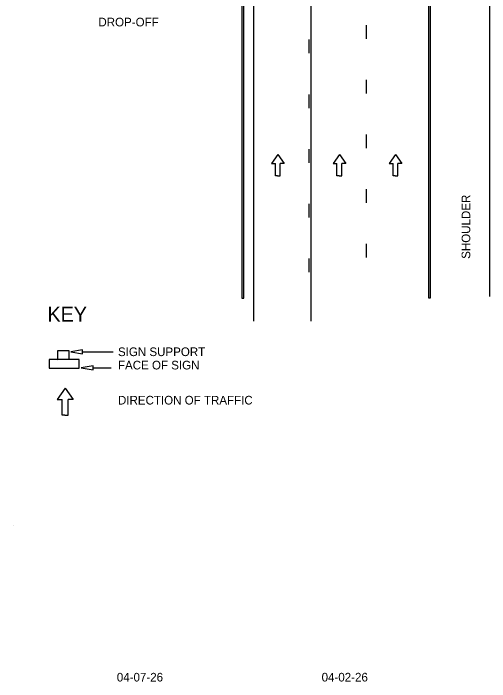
# Model space of a CAD drawing. Extents: x 1531.2 to 1543.2, y 1529.6 to 1539.7.
# Drawn here: x 1531.208 to 1534.518, y 1529.661 to 1534.302 of the extents above; entities that cross this region are included whole.
import ezdxf

# ---------------------------------------------------------------- set-up
doc = ezdxf.new("R2010")
doc.units = 0
for name, color, linetype in [('DETL-DIMS', 7, 'Continuous'), ('DETL-LINE', 7, 'Continuous'), ('DETL-NOTE', 7, 'Continuous'), ('DETL-TITL', 7, 'Continuous'), ('TTLB-TEXT', 7, 'Continuous'), ('USER-BORD', 7, 'Continuous')]:
    doc.layers.add(name, color=color, linetype=linetype)

# ---------------------------------------------------------------- blocks, each defined once
blk = doc.blocks.new('SIGN13')
at = {"layer": 'USER-BORD'}
for points in [[(-0.0134, 0.0182), (0.011, 0.0189), (0.011, 0.0371), (-0.0134, 0.0371)], [(-0.0314, 0.0182), (-0.0314, 0), (0.032, 0), (0.032, 0.0182)]]:
    blk.add_lwpolyline(points, close=True, dxfattribs=at)
blk = doc.blocks.new('DIR2')
at = {"layer": 'USER-BORD'}
for p, q in [((0, 0.0012), (-0.0342, -0.0477)), ((0, 0.0012), (0.0342, -0.0477)), ((-0.0342, -0.0477), (-0.0132, -0.0477)), ((-0.0132, -0.1133), (-0.0132, -0.0477)), ((0.0342, -0.0477), (0.0132, -0.0477)), ((0.0132, -0.1133), (0.0132, -0.0477)), ((-0.0011, -0.1133), (-0.0132, -0.1133)), ((-0.0011, -0.1133), (0.0011, -0.1133)), ((0.0011, -0.1133), (0.0132, -0.1133))]:
    blk.add_line(p, q, dxfattribs=at)
blk = doc.blocks.new('TD')
at = {"layer": 'USER-BORD'}
for p, q in [((0, 0), (-0.0539, -0.077)), ((0, 0), (0.0539, -0.077)), ((-0.0539, -0.077), (-0.0208, -0.077)), ((-0.0208, -0.1803), (-0.0208, -0.077)), ((0.0208, -0.1803), (0.0208, -0.077)), ((0.0539, -0.077), (0.0208, -0.077)), ((-0.0017, -0.1803), (-0.0208, -0.1803)), ((-0.0017, -0.1803), (0.0017, -0.1803)), ((0.0017, -0.1803), (0.0208, -0.1803))]:
    blk.add_line(p, q, dxfattribs=at)

msp = doc.modelspace()

# ---------------------------------------------------------------- linework, layer by layer
at = {"layer": 'DETL-DIMS'}
for p, q in [((1531.6883, 1531.9518), (1531.9006, 1531.9518)), ((1531.7616, 1531.8409), (1531.8873, 1531.8409))]:
    msp.add_line(p, q, dxfattribs=at)
for points in [[(1531.6883, 1531.9381), (1531.6883, 1531.9654), (1531.6065, 1531.9518)], [(1531.7616, 1531.8272), (1531.7616, 1531.8545), (1531.6798, 1531.8409)]]:
    msp.add_lwpolyline(points, close=True, dxfattribs=at)
at = {"layer": 'DETL-LINE'}
for p, q in [((1534.5179, 1537.343), (1534.5179, 1532.3345)), ((1533.2758, 1537.2325), (1533.2758, 1532.1635)), ((1532.8772, 1537.131), (1532.8772, 1532.1635))]:
    msp.add_line(p, q, dxfattribs=at)
for points in [[(1532.7952, 1532.3245), (1532.8102, 1532.3245), (1532.8102, 1537.3431), (1532.7952, 1537.3431)], [(1534.0925, 1532.326), (1534.1075, 1532.326), (1534.1075, 1537.343), (1534.0925, 1537.343)]]:
    msp.add_lwpolyline(points, close=True, dxfattribs=at)
for points in [[(1533.6602, 1534.221), (1533.6602, 1534.126)], [(1533.2616, 1534.1195), (1533.2616, 1534.0245)], [(1533.6602, 1533.841), (1533.6602, 1533.746)], [(1533.2616, 1533.7395), (1533.2616, 1533.6445)], [(1533.6602, 1533.461), (1533.6602, 1533.366)], [(1533.2616, 1533.3595), (1533.2616, 1533.2645)], [(1533.6602, 1533.081), (1533.6602, 1532.986)], [(1533.2616, 1532.9795), (1533.2616, 1532.8845)], [(1533.6602, 1532.701), (1533.6602, 1532.606)], [(1533.2616, 1532.5995), (1533.2616, 1532.5045)]]:
    msp.add_lwpolyline(points, dxfattribs=at)
at = {"layer": 'TTLB-TEXT'}
msp.add_line((1531.208, 1530.7453), (1531.208, 1530.7453), dxfattribs=at)

# ---------------------------------------------------------------- block references
at = {"layer": 'DETL-LINE'}
for name, p, xscale, yscale in [('TD', (1533.0461, 1533.3221), 0.81811764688, 0.81811764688), ('TD', (1533.4739, 1533.3221), 0.81811764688, 0.81811764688), ('TD', (1533.8638, 1533.3221), 0.81811764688, 0.81811764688), ('SIGN13', (1531.5596, 1531.8376), 3.27247058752, 3.27247058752), ('DIR2', (1531.5684, 1531.6975), 1.63623529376, 1.63623529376)]:
    msp.add_blockref(name, p, dxfattribs=dict(at, xscale=xscale, yscale=yscale))

# ---------------------------------------------------------------- texts
at = {"layer": 'DETL-NOTE'}
for s, p in [('DROP-OFF', (1531.7991, 1534.2116)), ('SIGN SUPPORT', (1531.9351, 1531.9217)), ('FACE OF SIGN', (1531.9351, 1531.829)), ('DIRECTION OF TRAFFIC', (1531.9351, 1531.5854))]:
    msp.add_text(s, height=0.06, dxfattribs=at).set_placement(p)
msp.add_text('SHOULDER', height=0.06, rotation=90, dxfattribs=at).set_placement((1534.3832, 1532.5971))
at = {"layer": 'DETL-TITL'}
msp.add_text('KEY', height=0.1026, dxfattribs=at).set_placement((1531.4447, 1532.1612))
at = {"layer": 'TTLB-TEXT'}
for s, p in [('04-07-26', (1531.9272, 1529.6615)), ('04-02-26', (1533.3503, 1529.6615))]:
    msp.add_text(s, height=0.06, dxfattribs=at).set_placement(p)

doc.saveas('drawing.dxf')
